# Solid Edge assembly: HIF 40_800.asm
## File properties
Title: Zylinder
Author: ahadarics
Template: iso assembly.asm
Last saved by: ahadarics
Revision: 81
Application: Solid Edge
Username: ahadarics
Dokumentum tartalom típus: 1
Document Number: HIF 40/800
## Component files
Kit_2.par
Kit_1.par
Profilrohr 40_800.par
Mutter.par
Kolbenstange 40_800.par
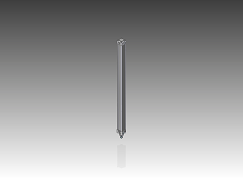
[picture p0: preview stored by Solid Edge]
